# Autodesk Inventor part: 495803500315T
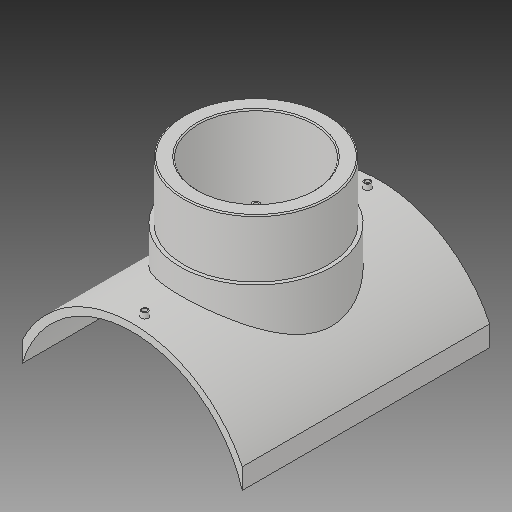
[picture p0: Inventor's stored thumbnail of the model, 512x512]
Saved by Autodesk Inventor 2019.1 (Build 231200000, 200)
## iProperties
Created: 2017-10
Part Number: 495803500315T
Material: Generic
Description: PLASSON BRANCH SADDLE 500x315
Document SubType Name: Modeling
Designer: KIM
Mass: 2754.05 g
Surface Area: 3037.44 cm^2
Volume: 2754.05 cm^3
Density: 1 g/cm^3
Appearance: Default
Author: KIM
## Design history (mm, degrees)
derived "495803.ipt"
feature "Solid1::495803.ipt"
tag "TaggingFeature1"
body "Solid1"
other parameters: "d1" = 16, "d4" = 0, "d12" = 277.1, "d13" = 14, "d14" = 243, "d16" = 5 deg, "d18" = 4, "d19" = 14, "d20" = 0, "d21" = 3, "d22" = 0, "d23" = 446, "d24" = 330.75, "d25" = 16, "d26" = 252, "d28" = 0, "d29" = 9.6, "d31" = 0, "d33" = 0, "d34" = 5, "d36" = 315, "d37" = 126, "d38" = 0, "d39" = 2.5, "d_1" = 315, "x_" = 16, "D_" = 16
